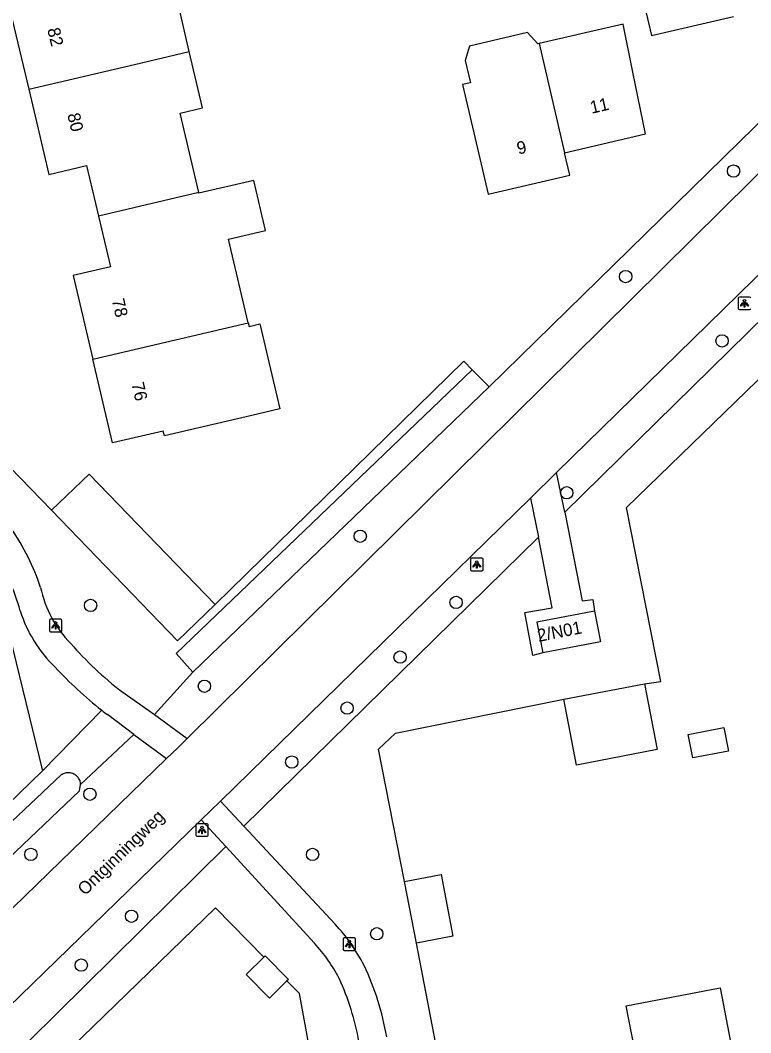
# Model space of a CAD drawing. Extents: x 157663 to 158496, y 379212 to 380934.
# Drawn here: x 158327.7 to 158385.6, y 380518.3 to 380598.7 of the extents above; entities that cross this region are included whole.
import ezdxf

# ---------------------------------------------------------------- set-up
doc = ezdxf.new("R2010")
doc.units = 0
for name, color, linetype in [('IMGEO_Boom', 7, 'Continuous'), ('IMGEO_Groenvoorziening', 7, 'Continuous'), ('IMGEO_Lichtpunt', 7, 'Continuous'), ('IMGEO_Openbare_ruimte_label', 7, 'Continuous'), ('IMGEO_Pand', 7, 'Continuous'), ('IMGEO_Pand_nummerreeks', 7, 'Continuous'), ('IMGEO_Rijbaan_lokaal_gesloten', 7, 'Continuous'), ('IMGEO_Voetpad_open', 7, 'Continuous'), ('IMGEO_Waterloop', 7, 'Continuous')]:
    doc.layers.add(name, color=color, linetype=linetype)

msp = doc.modelspace()

# ---------------------------------------------------------------- linework, layer by layer
at = {"layer": 'IMGEO_Boom'}
for centre in [(158384.275, 380586.728), (158375.709, 380578.346), (158383.355, 380573.243), (158371.031, 380561.18), (158354.642, 380557.734), (158333.252, 380552.24), (158362.25, 380552.479), (158357.808, 380548.135), (158342.279, 380545.823), (158353.607, 380544.084), (158349.217, 380539.804), (158333.193, 380537.248), (158328.512, 380532.472), (158350.866, 380532.464), (158336.5, 380527.561), (158355.958, 380526.167), (158332.514, 380523.676)]:
    msp.add_circle(centre, 0.489, dxfattribs=at)
at = {"layer": 'IMGEO_Groenvoorziening'}
for points in [[(158406.998, 380610.849), (158364.877, 380569.587)], [(158399.536, 380591.475), (158401.344, 380589.566), (158370.878, 380559.638)], [(158377.21, 380546.023), (158378.498, 380546.199), (158375.774, 380560.002), (158398.226, 380581.805)], [(158363.54, 380570.941), (158362.865, 380571.624), (158343.133, 380552.316)], [(158330.152, 380559.787), (158325.171, 380564.899)], [(158320.483, 380559.775), (158325.742, 380554.195), (158329.422, 380539.101)], [(158368.782, 380557.666), (158345.406, 380534.705)], [(158341.366, 380546.936), (158338.333, 380543.579)], [(158358.17, 380530.311), (158356.086, 380540.817), (158357.452, 380542.104), (158370.793, 380544.787)], [(158334.137, 380543.912), (158329.422, 380539.101)], [(158332.462, 380538.012), (158336.691, 380542)], [(158329.422, 380539.101), (158289.215, 380500), (158272.525, 380483.772), (158271.474, 380485.392), (158270.597, 380487.114), (158269.906, 380488.917), (158269.406, 380490.783), (158269.143, 380492.356), (158268.772, 380494.324), (158268.197, 380496.241), (158267.425, 380498.089), (158266.367, 380500), (158265.516, 380501.245), (158264.187, 380502.857), (158262.697, 380504.321), (158261.062, 380505.621), (158257.353, 380520.65)], [(158343.973, 380533.099), (158310.494, 380500), (158310.095, 380499.607)], [(158346.995, 380524.313), (158343.154, 380528.231), (158314.078, 380500), (158287.061, 380473.748), (158290.289, 380468.019), (158292.901, 380461.983), (158293.548, 380460.157), (158297.957, 380448.38), (158299.09, 380445.455), (158299.464, 380444.4), (158299.946, 380443.389), (158300.531, 380442.435), (158301.507, 380441.214)], [(158362.172, 380509.465), (158362.125, 380509.711), (158359.11, 380525.427)], [(158351.473, 380512.429), (158349.828, 380521.424), (158348.835, 380522.437)]]:
    msp.add_lwpolyline(points, dxfattribs=at)
at = {"layer": 'IMGEO_Lichtpunt'}
for p, q in [((158384.638, 380576.628), (158384.638, 380575.821)), ((158384.638, 380576.628), (158384.638, 380575.821)), ((158385.54, 380576.723), (158384.732, 380576.723)), ((158385.54, 380576.723), (158384.732, 380576.723)), ((158384.732, 380575.727), (158385.54, 380575.727)), ((158384.732, 380575.727), (158385.54, 380575.727)), ((158363.394, 380555.89), (158363.394, 380555.083)), ((158363.394, 380555.89), (158363.394, 380555.083)), ((158364.296, 380555.985), (158363.488, 380555.985)), ((158364.296, 380555.985), (158363.488, 380555.985)), ((158364.39, 380555.083), (158364.39, 380555.89)), ((158364.39, 380555.083), (158364.39, 380555.89)), ((158363.488, 380554.989), (158364.296, 380554.989)), ((158363.488, 380554.989), (158364.296, 380554.989)), ((158329.977, 380551.051), (158329.977, 380550.244)), ((158329.977, 380551.051), (158329.977, 380550.244)), ((158330.879, 380551.146), (158330.071, 380551.146)), ((158330.879, 380551.146), (158330.071, 380551.146)), ((158330.973, 380550.244), (158330.973, 380551.051)), ((158330.973, 380550.244), (158330.973, 380551.051)), ((158330.071, 380550.15), (158330.879, 380550.15)), ((158330.071, 380550.15), (158330.879, 380550.15)), ((158341.592, 380534.809), (158341.592, 380534.002)), ((158341.592, 380534.809), (158341.592, 380534.002)), ((158342.494, 380534.904), (158341.686, 380534.904)), ((158342.494, 380534.904), (158341.686, 380534.904)), ((158342.588, 380534.002), (158342.588, 380534.809)), ((158342.588, 380534.002), (158342.588, 380534.809)), ((158341.686, 380533.908), (158342.494, 380533.908)), ((158341.686, 380533.908), (158342.494, 380533.908)), ((158353.286, 380525.751), (158353.286, 380524.944)), ((158353.286, 380525.751), (158353.286, 380524.944)), ((158354.188, 380525.846), (158353.38, 380525.846)), ((158354.188, 380525.846), (158353.38, 380525.846)), ((158354.282, 380524.944), (158354.282, 380525.751)), ((158354.282, 380524.944), (158354.282, 380525.751)), ((158353.38, 380524.85), (158354.188, 380524.85)), ((158353.38, 380524.85), (158354.188, 380524.85))]:
    msp.add_line(p, q, dxfattribs=at)
for points in [[(158385.012, 380576.292), (158385.051, 380576.264), (158384.863, 380576.002), (158384.825, 380576.029), (158385.012, 380576.292)], [(158385.114, 380576.244), (158385.161, 380576.244), (158385.161, 380575.922), (158385.114, 380575.922), (158385.114, 380576.244)], [(158385.224, 380576.264), (158385.262, 380576.291), (158385.449, 380576.029), (158385.41, 380576.001), (158385.224, 380576.264)], [(158363.768, 380555.554), (158363.807, 380555.526), (158363.619, 380555.264), (158363.581, 380555.291), (158363.768, 380555.554)], [(158363.87, 380555.506), (158363.917, 380555.506), (158363.917, 380555.184), (158363.87, 380555.184), (158363.87, 380555.506)], [(158363.98, 380555.526), (158364.018, 380555.553), (158364.205, 380555.291), (158364.166, 380555.263), (158363.98, 380555.526)], [(158330.351, 380550.715), (158330.39, 380550.687), (158330.202, 380550.425), (158330.164, 380550.452), (158330.351, 380550.715)], [(158330.453, 380550.667), (158330.5, 380550.667), (158330.5, 380550.345), (158330.453, 380550.345), (158330.453, 380550.667)], [(158330.563, 380550.687), (158330.601, 380550.714), (158330.788, 380550.452), (158330.749, 380550.424), (158330.563, 380550.687)], [(158341.966, 380534.473), (158342.005, 380534.445), (158341.817, 380534.183), (158341.779, 380534.21), (158341.966, 380534.473)], [(158342.068, 380534.425), (158342.115, 380534.425), (158342.115, 380534.103), (158342.068, 380534.103), (158342.068, 380534.425)], [(158342.178, 380534.445), (158342.216, 380534.472), (158342.403, 380534.21), (158342.364, 380534.182), (158342.178, 380534.445)], [(158353.66, 380525.415), (158353.699, 380525.387), (158353.511, 380525.125), (158353.473, 380525.152), (158353.66, 380525.415)], [(158353.762, 380525.367), (158353.809, 380525.367), (158353.809, 380525.045), (158353.762, 380525.045), (158353.762, 380525.367)], [(158353.872, 380525.387), (158353.91, 380525.414), (158354.097, 380525.152), (158354.058, 380525.124), (158353.872, 380525.387)]]:
    msp.add_lwpolyline(points, dxfattribs=at)
for centre in [(158385.137, 380576.426), (158363.893, 380555.688), (158330.476, 380550.849), (158342.091, 380534.607), (158353.785, 380525.549)]:
    msp.add_circle(centre, 0.0994, dxfattribs=at)
for centre, start, end in [((158384.732, 380576.628), 90, 180), ((158384.732, 380576.628), 90, 180), ((158385.54, 380576.628), 0, 90), ((158385.54, 380576.628), 0, 90), ((158384.732, 380575.821), 180, 270), ((158384.732, 380575.821), 180, 270), ((158385.54, 380575.821), 270, 0), ((158385.54, 380575.821), 270, 360), ((158363.488, 380555.89), 90, 180), ((158363.488, 380555.89), 90, 180), ((158364.296, 380555.89), 0, 90), ((158364.296, 380555.89), 0, 90), ((158363.488, 380555.083), 180, 270), ((158363.488, 380555.083), 180, 270), ((158364.296, 380555.083), 270, 0), ((158364.296, 380555.083), 270, 360), ((158330.071, 380551.051), 90, 180), ((158330.071, 380551.051), 90, 180), ((158330.879, 380551.051), 0, 90), ((158330.879, 380551.051), 0, 90), ((158330.071, 380550.244), 180, 270), ((158330.071, 380550.244), 180, 270), ((158330.879, 380550.244), 270, 0), ((158330.879, 380550.244), 270, 360), ((158341.686, 380534.809), 90, 180), ((158341.686, 380534.809), 90, 180), ((158342.494, 380534.809), 0, 90), ((158342.494, 380534.809), 0, 90), ((158341.686, 380534.002), 180, 270), ((158341.686, 380534.002), 180, 270), ((158342.494, 380534.002), 270, 0), ((158342.494, 380534.002), 270, 360), ((158353.38, 380525.751), 90, 180), ((158353.38, 380525.751), 90, 180), ((158354.188, 380525.751), 0, 90), ((158354.188, 380525.751), 0, 90), ((158353.38, 380524.944), 180, 270), ((158353.38, 380524.944), 180, 270), ((158354.188, 380524.944), 270, 0), ((158354.188, 380524.944), 270, 360)]:
    msp.add_arc(centre, 0.0946, start, end, dxfattribs=at)
at = {"layer": 'IMGEO_Pand'}
for points in [[(158381.83, 380609.478), (158381.654, 380609.437), (158381.446, 380610.335), (158376.731, 380609.229), (158375.716, 380613.518), (158372.215, 380612.69), (158373.907, 380605.539), (158375.775, 380605.973), (158376.615, 380602.359), (158377.747, 380597.488), (158384.261, 380599.002)], [(158341.079, 380596.218), (158340.293, 380599.565), (158341.285, 380599.798), (158340.447, 380603.365), (158344.507, 380604.318), (158343.563, 380608.34)], [(158335.471, 380606.44), (158335.522, 380606.223), (158334.945, 380606.088), (158335.807, 380602.417), (158330.832, 380601.249), (158330.899, 380600.962), (158326.747, 380599.987), (158328.336, 380593.222)], [(158370.862, 380588.184), (158377.285, 380589.677), (158376.288, 380594.577), (158375.511, 380598.395), (158368.851, 380596.846)], [(158368.851, 380596.846), (158368.73, 380596.818), (158367.907, 380597.716), (158363.32, 380596.65), (158362.977, 380595.512), (158363.389, 380593.737), (158362.769, 380593.593), (158363.661, 380589.755), (158364.793, 380584.884), (158371.278, 380586.391), (158370.862, 380588.184)], [(158368.851, 380596.846), (158370.862, 380588.184)], [(158328.336, 380593.222), (158336.725, 380595.194), (158341.079, 380596.218)], [(158341.839, 380585.012), (158340.355, 380591.329), (158342.13, 380591.746), (158341.079, 380596.218)], [(158328.336, 380593.222), (158329.924, 380586.459), (158332.936, 380587.167), (158333.881, 380583.142)], [(158345.767, 380574.676), (158344.206, 380581.325), (158347.123, 380582.01), (158346.192, 380585.974), (158341.852, 380584.956), (158341.839, 380585.012)], [(158341.839, 380585.012), (158333.881, 380583.142)], [(158333.881, 380583.142), (158334.826, 380579.12), (158331.874, 380578.426), (158333.435, 380571.78)], [(158333.435, 380571.78), (158345.767, 380574.676)], [(158345.767, 380574.676), (158345.835, 380574.387), (158346.68, 380574.586), (158348.262, 380567.85), (158346.04, 380567.328), (158339.106, 380565.7), (158339.016, 380566.082), (158334.995, 380565.137), (158333.435, 380571.78)], [(158343.133, 380552.316), (158333.141, 380562.67), (158330.152, 380559.787)], [(158343.133, 380552.316), (158340.144, 380549.433), (158330.152, 380559.787)], [(158373.237, 380551.784), (158368.655, 380550.901), (158369.124, 380548.466)], [(158373.237, 380551.784), (158373.706, 380549.349), (158369.124, 380548.466)], [(158370.793, 380544.787), (158377.21, 380546.023)], [(158377.21, 380546.023), (158378.217, 380540.798), (158371.799, 380539.562), (158370.793, 380544.787)], [(158381.041, 380540.134), (158380.682, 380541.996), (158383.499, 380542.539), (158383.858, 380540.676), (158381.041, 380540.134)], [(158358.17, 380530.311), (158361.062, 380530.868), (158362.003, 380525.984), (158359.11, 380525.427)], [(158359.11, 380525.427), (158358.17, 380530.311)], [(158348.835, 380522.437), (158347.446, 380521.058), (158345.594, 380522.922), (158346.995, 380524.313)], [(158346.995, 380524.313), (158347.095, 380524.412), (158348.946, 380522.548), (158348.835, 380522.437)], [(158372.752, 380516.343), (158376.407, 380517.047), (158375.753, 380520.441), (158383.199, 380521.875), (158384.371, 380515.791), (158380.582, 380515.062), (158381.881, 380508.316), (158377.849, 380507.539), (158377.739, 380508.108), (158374.457, 380507.476)]]:
    msp.add_lwpolyline(points, dxfattribs=at)
at = {"layer": 'IMGEO_Rijbaan_lokaal_gesloten'}
for points in [[(158340.902, 380541.658), (158395.1, 380595.292)], [(158370.231, 380562.8), (158399.1, 380591.047)], [(158368.152, 380560.765), (158370.231, 380562.8)], [(158343.552, 380536.694), (158368.152, 380560.765)], [(158340.902, 380541.658), (158340.139, 380540.911), (158339.285, 380540.082)], [(158339.285, 380540.082), (158298.039, 380500), (158277.441, 380479.984), (158272.883, 380475.555)], [(158342.036, 380535.216), (158343.552, 380536.694)], [(158278.68, 380473.614), (158279.097, 380474.018), (158282.116, 380476.953), (158305.818, 380500), (158341.944, 380535.126), (158342.036, 380535.216)]]:
    msp.add_lwpolyline(points, dxfattribs=at)
at = {"layer": 'IMGEO_Voetpad_open'}
for points in [[(158370.878, 380559.638), (158370.231, 380562.8)], [(158368.152, 380560.765), (158368.782, 380557.666)], [(158370.878, 380559.638), (158372.269, 380552.602), (158373.094, 380552.706), (158373.237, 380551.784)], [(158369.124, 380548.466), (158368.336, 380548.259), (158367.703, 380551.672), (158369.885, 380552.048), (158368.782, 380557.666)], [(158335.722, 380545.396), (158338.333, 380543.579)], [(158336.691, 380542), (158334.581, 380543.569)], [(158338.333, 380543.579), (158340.902, 380541.658)], [(158336.691, 380542), (158339.285, 380540.082)], [(158345.406, 380534.705), (158343.552, 380536.694)], [(158342.036, 380535.216), (158343.973, 380533.099)], [(158352.65, 380526.936), (158345.406, 380534.705)], [(158351.008, 380525.41), (158343.973, 380533.099)]]:
    msp.add_lwpolyline(points, dxfattribs=at)
for centre, radius, start, end in [((158311.395, 380547.703), 18.853, 18.45883, 34.29641), ((158310.761, 380547.001), 17.577, 15.85817, 32.92978), ((158338.06, 380555.514), 8.973, 191.84311, 224.6635), ((158337.71, 380554.934), 10.517, 197.31667, 226.25966), ((158353.134, 380567.929), 28.476, 221.10812, 232.30498), ((158353.489, 380568.528), 31.312, 222.59433, 231.82755), ((158347.734, 380561.055), 21.881, 231.5785, 233.04771), ((158341.844, 380516.894), 14.751, 27.25978, 42.89966), ((158341.817, 380516.875), 12.543, 27.28457, 42.87877), ((158334.971, 380514.214), 22.102, 9.7924, 25.27612), ((158334.983, 380514.216), 19.851, 9.79292, 25.06416)]:
    msp.add_arc(centre, radius, start, end, dxfattribs=at)
at = {"layer": 'IMGEO_Waterloop'}
for points in [[(158363.54, 380570.941), (158340.029, 380548.417), (158341.366, 380546.936)], [(158364.877, 380569.587), (158363.54, 380570.941)], [(158364.877, 380569.587), (158341.366, 380546.936)], [(158332.462, 380538.012), (158332.454, 380538.099), (158332.439, 380538.186), (158332.415, 380538.271), (158332.385, 380538.353), (158332.347, 380538.432), (158332.302, 380538.508), (158332.251, 380538.579), (158332.193, 380538.645), (158332.13, 380538.706), (158332.061, 380538.761), (158331.988, 380538.81), (158331.911, 380538.852), (158331.831, 380538.887), (158331.747, 380538.914), (158331.662, 380538.934), (158331.575, 380538.947), (158331.487, 380538.951), (158331.399, 380538.948), (158331.312, 380538.937), (158331.226, 380538.918), (158331.143, 380538.891), (158331.062, 380538.857), (158330.984, 380538.816), (158330.921, 380538.776), (158289.923, 380500)], [(158273.465, 380481.728), (158274.224, 380482.069), (158293.02, 380500), (158332.358, 380537.527), (158332.462, 380538.012)]]:
    msp.add_lwpolyline(points, dxfattribs=at)

# ---------------------------------------------------------------- texts
at = {"layer": 'IMGEO_Openbare_ruimte_label'}
msp.add_text('Ontginningweg', height=1, rotation=44.31167, dxfattribs=at).set_placement((158332.807, 380529.149))
at = {"layer": 'IMGEO_Pand_nummerreeks'}
for s, rotation, p in [('82', 283.2162, (158329.806, 380597.988)), ('11', 13.08636, (158373.006, 380591.269)), ('80', 283.2162, (158331.395, 380591.218)), ('9', 13.08063, (158367.197, 380588.03)), ('78', 283.21793, (158334.92, 380576.481)), ('76', 283.21673, (158336.479, 380569.84)), ('2/N01', 11.17658, (158368.803, 380549.338))]:
    msp.add_text(s, height=1, rotation=rotation, dxfattribs=at).set_placement(p)

doc.saveas('drawing.dxf')
